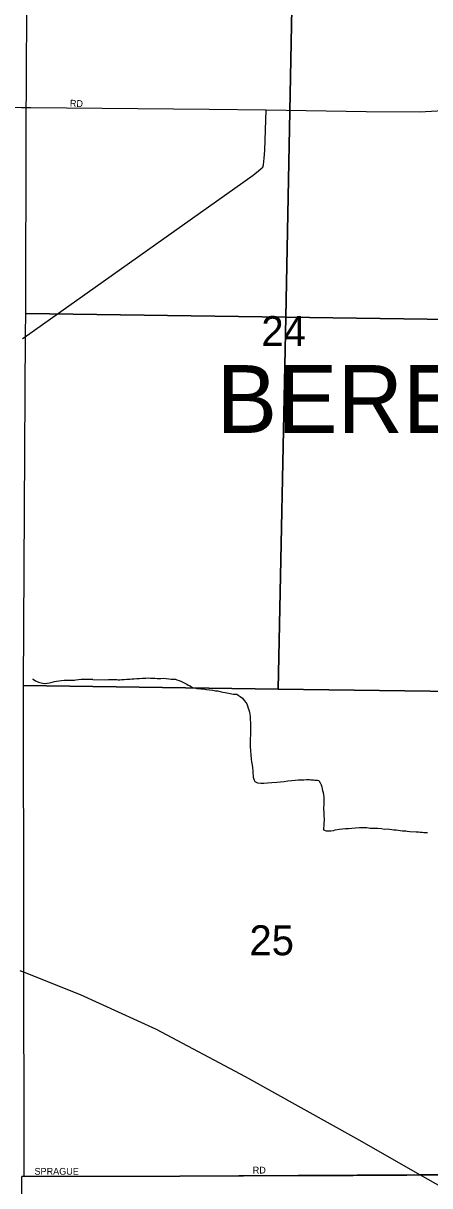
# Model space of a CAD drawing. Extents: x 2010165 to 2382125, y 1060529 to 1407316.
# Drawn here: x 2139658 to 2142658, y 1221171 to 1229747 of the extents above; entities that cross this region are included whole.
import ezdxf

# ---------------------------------------------------------------- set-up
doc = ezdxf.new("R2010")
doc.units = 0
for name, color, linetype in [('GM_X_City_Street', 7, 'Continuous'), ('GM_X_City_Street_Text', 7, 'Continuous'), ('GM_X_Corporation', 7, 'Continuous'), ('GM_X_Corporation_Text', 7, 'Continuous'), ('GM_X_Interstate_Route', 7, 'Continuous'), ('GM_X_Minor_River', 7, 'Continuous'), ('GM_X_Section', 7, 'Continuous'), ('GM_X_Section_Text', 7, 'Continuous')]:
    doc.layers.add(name, color=color, linetype=linetype)

msp = doc.modelspace()

# ---------------------------------------------------------------- linework, layer by layer
at = {"layer": 'GM_X_City_Street'}
for points in [[(2141028.6, 1229111.9), (2141449.4, 1229107.7), (2142187.5, 1229094.6), (2142583.5, 1229094.3), (2142711.5, 1229101.5), (2142823.2, 1229128.6), (2142919, 1229157.6), (2143054.6, 1229209), (2143254.1, 1229265), (2143401.8, 1229298.5), (2143459.7, 1229315.1), (2143565.4, 1229340.1), (2143661.4, 1229349.1), (2143747.3, 1229361.9), (2143797.2, 1229368.4), (2143869.2, 1229367.1)], [(2134243.2, 1229179.9), (2134256.4, 1229179.8), (2139645.3, 1229125.8), (2139713.6, 1229125.1)], [(2139665.3, 1227428.9), (2141353.8, 1228625.8), (2141393.2, 1228658.9), (2141414.5, 1228676.5), (2141424.7, 1228685.8), (2141430.2, 1228701.5), (2141436.7, 1228751.5), (2141440.6, 1228807.3), (2141449.4, 1229107.7)], [(2139713.6, 1229125.1), (2139713.6, 1229125.1), (2141028.6, 1229111.9), (2141028.6, 1229111.9)], [(2139653.1, 1227420.2), (2139665.3, 1227428.9)], [(2139646.1, 1221239.5), (2140813.5, 1221242), (2142121.3, 1221250.2), (2142587.6, 1221252.6), (2142825.7, 1221254.1), (2143061.9, 1221255.7)]]:
    msp.add_lwpolyline(points, dxfattribs=at)
at = {"layer": 'GM_X_Corporation'}
for points in [[(2139563.1, 1207294.1), (2139646.1, 1221239.5), (2140813.5, 1221242), (2142121.3, 1221250.2), (2142587.6, 1221252.6), (2142825.7, 1221254.1), (2144579, 1220185.1)], [(2144579, 1220185.1), (2142825.7, 1221254.1), (2142587.6, 1221252.6), (2142121.3, 1221250.2), (2140813.5, 1221242), (2139646.1, 1221239.5)]]:
    msp.add_lwpolyline(points, dxfattribs=at)
at = {"layer": 'GM_X_Interstate_Route'}
for points in [[(2139632.9, 1222759.9), (2139651.5, 1222752.4), (2140077, 1222581.4), (2140639.4, 1222327.4), (2141295.9, 1221976.7), (2142116.7, 1221519.6), (2142587.6, 1221252.6)], [(2142587.6, 1221252.6), (2143470.5, 1220752.7), (2144195.2, 1220350.1), (2144298.5, 1220297.2), (2144576.6, 1220152), (2144969.7, 1219962.8)]]:
    msp.add_lwpolyline(points, dxfattribs=at)
at = {"layer": 'GM_X_Minor_River'}
for points in [[(2139726.2, 1224910.4), (2139730.2, 1224908.5), (2139748.4, 1224896.7), (2139770.6, 1224887), (2139790.8, 1224881.3), (2139802.9, 1224877.5), (2139816.9, 1224875.7), (2139832.9, 1224877.9), (2139850.9, 1224882.2), (2139870.9, 1224886.5), (2139888.9, 1224890.8), (2139902.9, 1224893), (2139920.9, 1224895.2), (2139940.9, 1224897.5), (2139959, 1224899.8), (2139977, 1224900.1), (2139997, 1224900.3), (2140017.1, 1224900.6), (2140035.1, 1224900.9), (2140045.1, 1224903.1), (2140065.1, 1224905.4), (2140085.2, 1224907.7), (2140095.2, 1224907.8), (2140113.2, 1224908.1), (2140171.5, 1224908.1)], [(2140171.5, 1224905.5), (2140261.2, 1224903), (2140287.2, 1224905.4), (2140347.3, 1224906.1), (2140359.3, 1224904.2), (2140371.4, 1224904.4), (2140385.4, 1224904.6), (2140403.4, 1224904.8), (2140421.4, 1224907), (2140445.4, 1224907.3), (2140459.4, 1224909.5), (2140475.5, 1224909.7), (2140495.5, 1224911.9), (2140515.5, 1224912.2), (2140537.5, 1224914.4), (2140561.6, 1224914.8), (2140579.6, 1224917), (2140595.6, 1224915.2), (2140611.6, 1224915.4), (2140629.7, 1224915.6), (2140645.7, 1224913.8), (2140671.8, 1224914.1), (2140691.8, 1224914.3), (2140711.8, 1224912.6), (2140731.9, 1224910.8), (2140750, 1224909), (2140766, 1224909.2), (2140780, 1224907.4), (2140792.1, 1224903.5), (2140808.2, 1224897.7), (2140824.3, 1224889.9), (2140844.5, 1224882.1), (2140864.6, 1224872.3), (2140874.8, 1224864.4), (2140888.9, 1224858.6), (2140901, 1224848.7), (2140913.1, 1224844.8), (2140925.1, 1224843), (2140939.2, 1224839.1), (2140953.2, 1224839.3), (2140967.3, 1224837.5), (2140987.3, 1224835.7), (2141007.4, 1224831.9), (2141031.5, 1224828.2), (2141055.6, 1224826.5), (2141075.7, 1224822.8), (2141093.7, 1224821), (2141111.8, 1224817.2), (2141129.9, 1224813.4), (2141148, 1224809.6), (2141210.2, 1224798.3), (2141224.3, 1224796.5), (2141234.3, 1224796.6), (2141244.4, 1224790.7), (2141258.5, 1224780.8), (2141274.7, 1224767), (2141289, 1224751.1), (2141301.2, 1224737.2), (2141307.3, 1224725.3), (2141311.5, 1224711.3), (2141317.8, 1224695.3), (2141321.9, 1224681.3), (2141326.2, 1224665.3), (2141330.4, 1224649.3), (2141332.6, 1224631.3), (2141332.9, 1224609.2), (2141335.2, 1224589.2), (2141335.3, 1224577.1), (2141335.5, 1224563.1), (2141335.8, 1224543), (2141334.1, 1224520.9), (2141334.4, 1224496.9), (2141332.7, 1224468.8), (2141333.1, 1224440.7), (2141331.5, 1224410.6), (2141333.9, 1224380.5), (2141336.3, 1224350.4), (2141338.7, 1224318.3), (2141343, 1224298.3), (2141347.3, 1224276.3), (2141349.6, 1224254.3), (2141351.8, 1224234.2), (2141352.1, 1224214.2), (2141354.3, 1224196.1), (2141354.5, 1224184.1), (2141360.8, 1224164.1), (2141366.9, 1224154.2), (2141387.1, 1224142.4), (2141411.2, 1224140.6), (2141433.2, 1224140.9), (2141461.2, 1224143.3), (2141491.2, 1224145.6), (2141529.3, 1224148.1), (2141557.3, 1224150.5), (2141583.3, 1224152.8), (2141611.3, 1224157.2), (2141639.3, 1224159.5), (2141663.3, 1224163.8), (2141687.3, 1224166.1), (2141709.4, 1224166.4), (2141727.4, 1224166.6)], [(2141727.4, 1224166.6), (2141747.4, 1224166.8), (2141759.4, 1224167), (2141769.4, 1224167.1), (2141779.5, 1224165.2), (2141789.5, 1224165.4), (2141799.5, 1224165.5), (2141809.6, 1224163.6), (2141819.6, 1224163.7), (2141829.6, 1224163.8), (2141839.7, 1224160), (2141849.9, 1224144), (2141856.1, 1224128.1), (2141860.3, 1224114.1), (2141864.5, 1224100.1), (2141866.7, 1224086.1), (2141870.9, 1224072.1), (2141873.1, 1224056), (2141875.3, 1224040), (2141875.6, 1224019.9), (2141875.9, 1223991.9), (2141874.5, 1223951.7), (2141874.8, 1223925.6), (2141875, 1223907.6), (2141875.2, 1223893.5), (2141877.4, 1223883.5), (2141877.5, 1223873.5), (2141877.6, 1223863.5), (2141875.8, 1223851.4), (2141875.9, 1223841.4), (2141874.5, 1223797.2), (2141892.6, 1223789.4), (2141904.6, 1223789.6), (2141918.7, 1223789.7), (2141928.7, 1223789.8), (2141946.7, 1223792.1), (2141960.6, 1223796.3), (2141990.6, 1223800.6), (2142012.6, 1223802.9), (2142034.6, 1223807.2), (2142058.7, 1223807.5), (2142082.7, 1223809.8), (2142108.7, 1223812.1), (2142138.7, 1223814.5), (2142166.8, 1223812.8), (2142192.8, 1223813.2), (2142216.9, 1223809.4), (2142241, 1223809.7), (2142275, 1223808.2), (2142301.1, 1223806.5), (2142323.2, 1223802.7), (2142343.2, 1223803), (2142361.3, 1223801.2), (2142377.3, 1223799.4), (2142393.4, 1223797.6), (2142409.4, 1223795.8), (2142423.5, 1223793.9), (2142439.5, 1223792.1), (2142457.6, 1223790.3), (2142469.6, 1223788.5), (2142481.7, 1223788.6), (2142491.7, 1223786.7), (2142509.8, 1223784.9), (2142557.9, 1223781.5), (2142573.9, 1223781.7), (2142588, 1223779.9), (2142602, 1223780.1), (2142614, 1223778.2), (2142626.1, 1223776.3), (2142636.1, 1223776.5), (2142642.1, 1223776.5)]]:
    msp.add_lwpolyline(points, dxfattribs=at)
at = {"layer": 'GM_X_Section'}
for points in [[(2139686.1, 1230258), (2141648.1, 1230239.3), (2141594.3, 1227579), (2139677.3, 1227606), (2139680.3, 1228952.7)], [(2141648.1, 1230239.3), (2143604.9, 1230220.8), (2143508.2, 1227552.1), (2141594.3, 1227579)], [(2141594.3, 1227579), (2141538.9, 1224835.3), (2139660.2, 1224861.3), (2139674.6, 1227452.9), (2139677.3, 1227606)], [(2143508.2, 1227552.1), (2143408.8, 1224809.4), (2141538.9, 1224835.3), (2141594.3, 1227579)], [(2141538.9, 1224835.3), (2143408.8, 1224809.4), (2143284.1, 1221252.1), (2142093.1, 1221244.5), (2139663.3, 1221236.3), (2139660.2, 1224861.3)]]:
    msp.add_lwpolyline(points, close=True, dxfattribs=at)

# ---------------------------------------------------------------- texts
at = {"layer": 'GM_X_City_Street_Text'}
for s, rotation, p in [('RD', 356.98902, (2140000.8, 1229133)), ('SPRAGUE', 0.00001, (2139740.7, 1221252.6)), ('RD', 0.00001, (2141351.1, 1221261.4))]:
    msp.add_text(s, height=50, rotation=rotation, dxfattribs=at).set_placement(p)
at = {"layer": 'GM_X_Corporation_Text'}
msp.add_text('BEREA', height=500, rotation=0.00001, dxfattribs=at).set_placement((2141084.9, 1226724.8))
at = {"layer": 'GM_X_Section_Text'}
for s, p in [('24', (2141414.9, 1227365.5)), ('25', (2141326.9, 1222871.5))]:
    msp.add_text(s, height=221, rotation=0.00001, dxfattribs=at).set_placement(p)

doc.saveas('drawing.dxf')
